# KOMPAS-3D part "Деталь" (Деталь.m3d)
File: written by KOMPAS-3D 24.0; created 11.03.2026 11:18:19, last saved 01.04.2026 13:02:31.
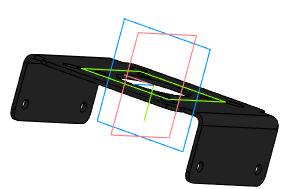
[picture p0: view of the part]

Document properties: Автор: R2D2; Полное имя файла: E:\Работа\Зайцев\Аксессуары для пневмоприводов\Блок концевых выключателей DN.ru\APL-310N Блок концевых выключателей DN.ru\исходные материалы\Деталь.m3d

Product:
- Part/product: Деталь
    Масса: 0.159642

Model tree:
1. Эскиз:1
2. Листовое тело:1
     Расстояние 1 = 80; Радиус сгиба = 3; Радиус сгиба = 3; Коэффициент = 0.4; Величина сгиба = 10; Радиус сгиба = 3; Коэффициент = 0.4; Величина сгиба = 10
3. Эскиз:4  (with: Грань.Листовое тело:1)
4. Элемент выдавливания:1
     Расстояние 2 = 33
5. Скругление:1  (with: Ребро.Элемент выдавливания:1)
     Радиус = 5
6. Зеркальный массив:2
7. Экземпляр ( 1 )
8. Экземпляр ( 2 )  (with: Элемент выдавливания:1, Скругление:1)
9. Эскиз:5  (with: Грань.Листовое тело:1)
10. Вырез в листовом теле:2
     Глубина выреза = 10
11. Массив по концентрической сетке:1  (with: Вырез в листовом теле:2, Эскиз:5)  (4 pattern instances)
     Шаг 2 = 360
12. Эскиз:6  (with: Грань.Листовое тело:1, Ребро.Листовое тело:1)
13. Элемент выдавливания:2
     Расстояние 2 = 104
14. Скругление:2  (with: Ребро.Элемент выдавливания:1)  (labels: Ребро.Элемент выдавливания:1.Экземпляр ( 2 ))
     Радиус = 5

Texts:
  Угловой размер с обрывом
